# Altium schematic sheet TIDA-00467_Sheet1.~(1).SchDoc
size 431 x 279 mm; Date: Not shown in title block; ApprovedBy: Not shown in title block; CheckedBy: Not shown in title block; Author: Not shown in title block; CompanyName: Not shown in title block; DrawnBy: Salil Chellappan; Engineer: Not shown in title block; Organization: Not shown in title block; Address1: Not shown in title block; Address2: Not shown in title block; Address3: Not shown in title block; Address4: Not shown in title block; DocumentNumber: 1; Revision: Use project parameter SCH_Rev; SheetNumber: 1; SheetTotal: 3; PageSetup: Record=PageOptions¦CenterHorizontal=True¦CenterVertical=True¦PrintScale=1.00¦XCorrection=1.00¦YCorrection=1.00¦PrintKind=0¦BorderSize=5000000¦LeftOffset=0¦BottomOffset=0¦Orientation=2¦PaperLength=1000¦PaperWidth=1000¦Scale=100¦PaperSource=15¦PrintQuality=600¦MediaType=1¦DitherType=10¦PaperKind=Letter¦PrintScaleMode=1
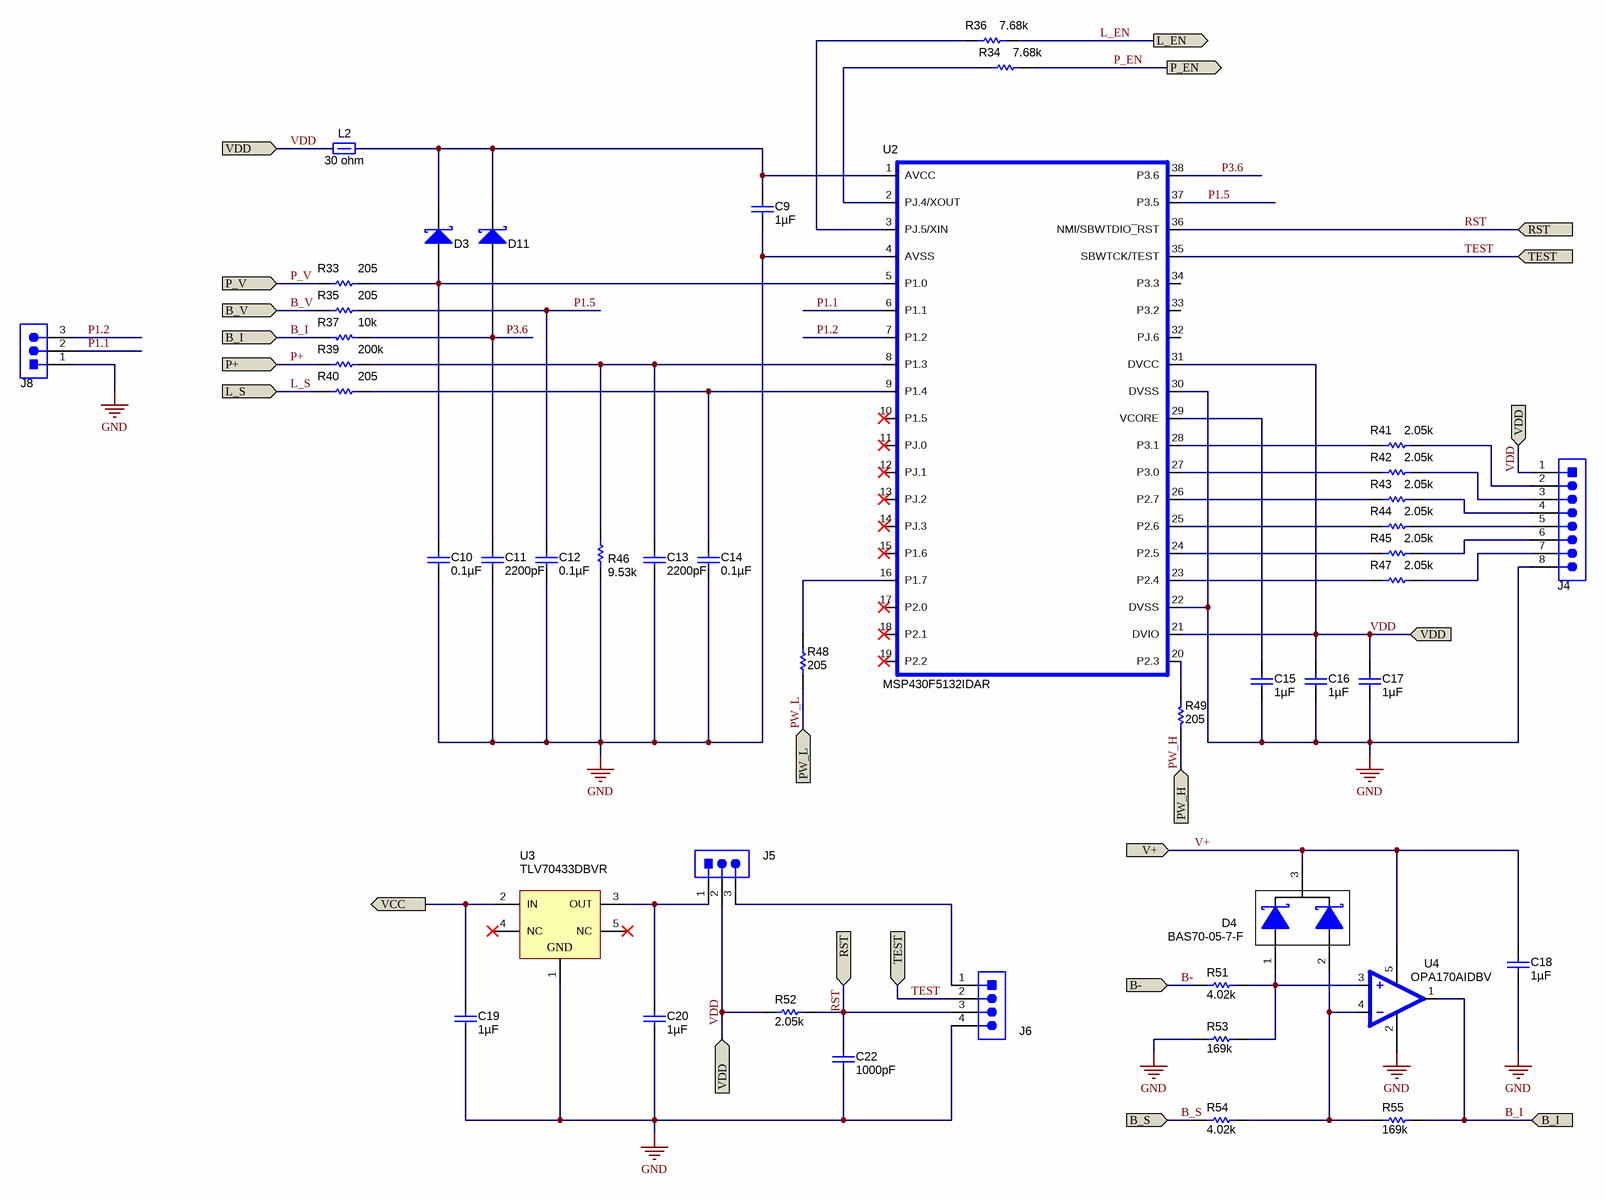
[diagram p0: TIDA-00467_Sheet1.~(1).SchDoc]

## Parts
C9  ValueDisplayed: 1µF  [0805_HV]  (hidden comment: 08055C105KAT2A)
C10  ValueDisplayed: 0.1µF  [0805_HV]  (hidden comment: 08053C104KAT2A)
C11  ValueDisplayed: 2200pF  [0805_HV]  (hidden comment: 08055C222KAT2A)
C12  ValueDisplayed: 0.1µF  [0805_HV]  (hidden comment: 08053C104KAT2A)
C13  ValueDisplayed: 2200pF  [0805_HV]  (hidden comment: 08055C222KAT2A)
C14  ValueDisplayed: 0.1µF  [0805_HV]  (hidden comment: 08053C104KAT2A)
C15  ValueDisplayed: 1µF  [0805_HV]  (hidden comment: 08055C105KAT2A)
C16  ValueDisplayed: 1µF  [0805_HV]  (hidden comment: 08055C105KAT2A)
C17  ValueDisplayed: 1µF  [0805_HV]  (hidden comment: 08055C105KAT2A)
C18  ValueDisplayed: 1µF  [0805_HV]  (hidden comment: 08055C105KAT2A)
C19  ValueDisplayed: 1µF  [0805_HV]  (hidden comment: 08055C105KAT2A)
C20  ValueDisplayed: 1µF  [0805_HV]  (hidden comment: 08055C105KAT2A)
C22  ValueDisplayed: 1000pF  [0805_HV]  (hidden comment: 08055C102KAT2A)
D3  BAS 52-02V H6327  [SOD-523]  (value not drawn)
D4  BAS70-05-7-F  [SOT-23]
D11  BAS 52-02V H6327  [SOD-523]  (value not drawn)
J4  TSW-108-07-G-S  [TSW-108-07-G-S]  (value not drawn)
J5  5-146278-3  [TE_5-146278-3]  (value not drawn)
J6  5-146278-4  [TE_5-146278-4]  (value not drawn)
J8  5-146278-3  [TE_5-146278-3]  (value not drawn)
L2  value 30 ohm  [0805_HV]  (hidden comment: MMZ2012R300A)
R33  value 205  [0805_HV]  (hidden comment: CRCW0805205RFKEA)
R34  ValueDisplayed: 7.68k  [0805_HV]  (hidden comment: CRCW08057K68FKEA)
R35  value 205  [0805_HV]  (hidden comment: CRCW0805205RFKEA)
R36  ValueDisplayed: 7.68k  [0805_HV]  (hidden comment: CRCW08057K68FKEA)
R37  value 10k  [0805_HV]  (hidden comment: CRCW080510K0JNEA)
R39  ValueDisplayed: 200k  [0805_HV]  (hidden comment: CRCW0805200KFKEA)
R40  value 205  [0805_HV]  (hidden comment: CRCW0805205RFKEA)
R41  value 2.05k  [0805_HV]  (hidden comment: CRCW08052K05FKEA)
R42  value 2.05k  [0805_HV]  (hidden comment: CRCW08052K05FKEA)
R43  value 2.05k  [0805_HV]  (hidden comment: CRCW08052K05FKEA)
R44  value 2.05k  [0805_HV]  (hidden comment: CRCW08052K05FKEA)
R45  value 2.05k  [0805_HV]  (hidden comment: CRCW08052K05FKEA)
R46  ValueDisplayed: 9.53k  [0805_HV]  (hidden comment: CRCW08059K53FKEA)
R47  value 2.05k  [0805_HV]  (hidden comment: CRCW08052K05FKEA)
R48  value 205  [0805_HV]  (hidden comment: CRCW0805205RFKEA)
R49  value 205  [0805_HV]  (hidden comment: CRCW0805205RFKEA)
R51  ValueDisplayed: 4.02k  [0805_HV]  (hidden comment: RT0805BRD074K02L)
R52  value 2.05k  [0805_HV]  (hidden comment: CRCW08052K05FKEA)
R53  ValueDisplayed: 169k  [0805_HV]  (hidden comment: RT0805BRD07169KL)
R54  ValueDisplayed: 4.02k  [0805_HV]  (hidden comment: RT0805BRD074K02L)
R55  ValueDisplayed: 169k  [0805_HV]  (hidden comment: RT0805BRD07169KL)
U2  MSP430F5132IDAR  [DA_38P]
U3  TLV70433DBVR  [DBV0005A_N]
U4  OPA170AIDBV  [SOT23-5P]

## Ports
B- (in), B_I (in), B_S (in), B_V (in), L_EN (out), L_S (in), P+ (in), P_EN (out), P_V (in), PW_H (in), PW_L (in), RST (in), TEST (in), V+, VCC, VDD, VDD (in)

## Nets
GND: C9.2 C10.2 C11.2 C12.2 C13.2 C14.2 C15.2 C16.2 C17.2 C18.2 C19.2 C20.2 C22.2 J4.8 J6.4 J8.1 R46.1 R53.1 U2.4(AVSS) U2.22(DVSS) U2.30(DVSS) U3.1(GND) U4.2(V-)
B-: R51.1 ; port B-
B_I: R37.2 R55.2 U4.1(OUT) ; port B_I
B_S: R54.1 ; port B_S
B_V: R35.1 ; port B_V
L_EN: R36.1 ; port L_EN
L_S: R40.1 ; port L_S
P1.1: J8.2 U2.6(P1.1)
P1.2: J8.3 U2.7(P1.2)
P1.5: C12.1 R35.2 U2.37(P3.5)
P3.6: C11.1 D11.2(A) R37.1 U2.38(P3.6)
P+: R39.1 ; port P+
P_EN: R34.1 ; port P_EN
P_V: R33.1 ; port P_V
PW_H: R49.1 ; port PW_H
PW_L: R48.1 ; port PW_L
RST: C22.1 J6.3 R52.2 U2.36(NMI/SBWTDIO~{_}RST) ; port RST
TEST: J6.2 U2.35(SBWTCK/TEST) ; port TEST
V+: C18.1 D4.3(K) U4.5(V+) ; port V+
VCC: C19.1 U3.2(IN) ; port VCC
VDD: C16.1 C17.1 J4.1 J5.2 L2.1 R52.1 U2.21(DVIO) U2.31(DVCC) ; port VDD
NetC9_1: C9.1 D3.1(K) D11.1(K) L2.2 U2.1(AVCC)
NetC10_1: C10.1 D3.2(A) R33.2 U2.5(P1.0)
NetC13_1: C13.1 R39.2 R46.2 U2.8(P1.3)
NetC14_1: C14.1 R40.2 U2.9(P1.4)
NetC15_1: C15.1 U2.29(VCORE)
NetC20_1: C20.1 J5.1 U3.3(OUT)
NetD4_1: D4.1(A) R51.2 R53.2 U4.3
NetD4_2: D4.2(A) R54.2 R55.1 U4.4
NetJ4_2: J4.2 R41.2
NetJ4_3: J4.3 R42.2
NetJ4_4: J4.4 R43.2
NetJ4_5: J4.5 R44.2
NetJ4_6: J4.6 R45.2
NetJ4_7: J4.7 R47.2
NetJ5_3: J5.3 J6.1
NetR34_2: R34.2 U2.2(PJ.4/XOUT)
NetR36_2: R36.2 U2.3(PJ.5/XIN)
NetR41_1: R41.1 U2.28(P3.1)
NetR42_1: R42.1 U2.27(P3.0)
NetR43_1: R43.1 U2.26(P2.7)
NetR44_1: R44.1 U2.25(P2.6)
NetR45_1: R45.1 U2.24(P2.5)
NetR47_1: R47.1 U2.23(P2.4)
NetR48_2: R48.2 U2.16(P1.7)
NetR49_2: R49.2 U2.20(P2.3)

Not connected (* = marked no-connect by the designer): U2 10(P1.5)* 11(PJ.0)* 12(PJ.1)* 13(PJ.2)* 14(PJ.3)* 15(P1.6)* 17(P2.0)* 18(P2.1)* 19(P2.2)* 32(PJ.6) 33(P3.2) 34(P3.3); U3 4(NC)* 5(NC)*

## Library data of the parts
C9 C15-C20 = 08055C105KAT2A: CAP, CERM, 1uF, 50V, +/-10%, X7R, 0805; Manufacturer: AVX; Polarized: N; CompType: Capacitor; U/M: EA; Cap_F: 0.000001; Tolerance_%: 10; Value1: Unknown; VDC_V: 50; TaMin_C: -55; TaMax_C: 125; Cap_Case: 0805
C10 C12 C14 = 08053C104KAT2A: CAP, CERM, 0.1uF, 25V, +/-10%, X7R, 0805; Manufacturer: AVX; Polarized: N; CompType: Capacitor; U/M: EA; Cap_F: 0.0000001; Tolerance_%: 10; ESR_Ohm: 0.28; Value1: 0.28 ohm; VDC_V: 25; TaMin_C: -55; TaMax_C: 125; Cap_Case: 0805
C11 C13 = 08055C222KAT2A: CAP, CERM, 2200 pF, 50 V, +/- 10%, X7R, 0805; Manufacturer: AVX; Polarized: N; CompType: Capacitor; Value: 2200pF; U/M: EA; Cap_F: 0.0000000022; Tolerance_%: 10; ESR_ohm: 0.183; Value1: 0.183 ohm; VDC_V: 50; Value2: 50V; TaMin_C: -55; TaMax_C: 125; Cap_Case: 0805
C22 = 08055C102KAT2A: CAP, CERM, 1000 pF, 50 V, +/- 10%, X7R, 0805; Manufacturer: AVX; Polarized: N; CompType: Capacitor; Value: 1000pF; U/M: EA; Cap_F: 0.000000001; Tolerance_%: 10; ESR_ohm: 0.29; Value1: 0.29 ohm; VDC_V: 50; Value2: 50V; TaMin_C: -55; TaMax_C: 125; Cap_Case: 0805
D3 D11 = BAS 52-02V H6327: Diode, Schottky, 45 V, 0.75 A, SOD-523; Manufacturer: Infineon Technologies; U/M: EA; Vf_V: 0.6; Value: 45V; Value1: 0.75A; Value2: 0.6V; Io_A: 0.75; Vr_V: 45; TJmax_C: 150
D4 = BAS70-05-7-F: Diode, Schottky, 70 V, 0.07 A, SOT-23; Manufacturer: Diodes Inc.; SymbolCreator: a0412235; U/M: EA; Vf_V: 1.7; Value: 70V; Value1: 0.07A; Value2: 1.7V; Io_A: 0.07; Vr_V: 70
J4 = TSW-108-07-G-S: Header, TH, 100mil, 8x1, Gold plated, 230 mil above insulator; Manufacturer: Samtec; SymbolCreator: a0411947; U/M: EA
J5 J8 = 5-146278-3: Header, 100mil, 3x1, Tin, TH; Manufacturer: TE Connectivity; SymbolCreator: a0799628; U/M: EA
J6 = 5-146278-4: Header, 100mil, 4x1, Tin, TH; Manufacturer: TE Connectivity; SymbolCreator: a0412235; U/M: EA
L2 = MMZ2012R300A: Ferrite Bead, 30 ohm @ 100MHz, 1.5A, 0805; Manufacturer: TDK; Imax_A: 1.5; DCR_ohm: 0.05; Value1: 0.05 ohm; ZTyp@100MHz_Ohm: 30
R33 R35 R40 R48 R49 = CRCW0805205RFKEA: RES, 205 ohm, 1%, 0.125W, 0805; Manufacturer: Vishay-Dale; CompType: Resistor; Value_Code: 205R; Tolerance_%: 1; Power_W: 0.125; VDC_V: 150; TempCo: 100 ppm/C; EIA_Code: E96; U/M: EA
R34 R36 = CRCW08057K68FKEA: RES, 7.68 k, 1%, 0.125 W, 0805; Manufacturer: Vishay-Dale; CompType: Resistor; Value: 7.68k; Res_ohm: 7680; Value_Code: 7k68; Tolerance_%: 1; Power_W: 0.125; Value2: 0.125W; VDC_V: 150; TempCo: 100 ppm/C; EIA_Code: E96; U/M: EA
R37 = CRCW080510K0JNEA: RES, 10k ohm, 5%, 0.125W, 0805; Manufacturer: Vishay-Dale; CompType: Resistor; Res_ohm: 10000; Value_Code: 10k0; Tolerance_%: 5; Power_W: 0.125; VDC_V: 150; TempCo: 200 ppm/C; EIA_Code: E24; U/M: EA
R39 = CRCW0805200KFKEA: RES, 200 k, 1%, 0.125 W, 0805; Manufacturer: Vishay-Dale; CompType: Resistor; Value: 200k; Res_ohm: 200000; Tolerance_%: 1; Power_W: 0.125; Value2: 0.125W; VDC_V: 150; TempCo: 100 ppm/C; EIA_Code: E96; U/M: EA
R41-R45 R47 R52 = CRCW08052K05FKEA: RES, 2.05k ohm, 1%, 0.125W, 0805; Manufacturer: Vishay-Dale; CompType: Resistor; Res_ohm: 2050; Value_Code: 2k05; Tolerance_%: 1; Power_W: 0.125; VDC_V: 150; TempCo: 100 ppm/C; EIA_Code: E96; U/M: EA
R46 = CRCW08059K53FKEA: RES, 9.53 k, 1%, 0.125 W, 0805; Manufacturer: Vishay-Dale; CompType: Resistor; Value: 9.53k; Res_ohm: 9530; Value_Code: 9k53; Tolerance_%: 1; Power_W: 0.125; Value2: 0.125W; VDC_V: 150; TempCo: 100 ppm/C; EIA_Code: E96; U/M: EA
R51 R54 = RT0805BRD074K02L: RES, 4.02 k, 0.1%, 0.125 W, 0805; Manufacturer: Yageo America; CompType: Resistor; Value: 4.02k; Res_ohm: 4020; Value_Code: 4k02; Tolerance_%: 0.1; Power_W: 0.125; Value2: 0.125W; VDC_V: 150; TempCo: 25 ppm/C; EIA_Code: E192; U/M: EA
R53 R55 = RT0805BRD07169KL: RES, 169 k, 0.1%, 0.125 W, 0805; Manufacturer: Yageo America; CompType: Resistor; Value: 169k; Res_ohm: 169000; Tolerance_%: 0.1; Power_W: 0.125; Value2: 0.125W; VDC_V: 150; TempCo: 25 ppm/C; EIA_Code: E192; U/M: EA
U2 = MSP430F5132IDAR: IC, MIXED SIGNAL MICROCONTROLLER; Manufacturer: TI; Alternate Manufacturer: None; Area: 330000
U3 = TLV70433DBVR: Single Output LDO, 150 mA, Fixed 3.3 V Output, 2.5 to 24 V Input, with Ultra-Low IQ, 5-pin SOT-23 (DBV), -40 to 125 degC, Green (RoHS & no Sb/Br); Manufacturer: Texas Instruments; Alternate Manufacturer: None; Alternate PartNumber: Equivalent; Accuracy(%): 2; Fixed Output Options(V): 3.3; Iout(Max)(A): 0.15; Iq(Typ)(mA): 0.003; SubFamily: Single Channel LDO; Vdo(Typ)(mV): 400; Vin(Max)(V): 24; Vin(Min)(V): 2.5
U4 = OPA170AIDBV: IC, 36V, Single-Supply, Op Amp; Manufacturer: TI; Alternate Manufacturer: None; Area: 8700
